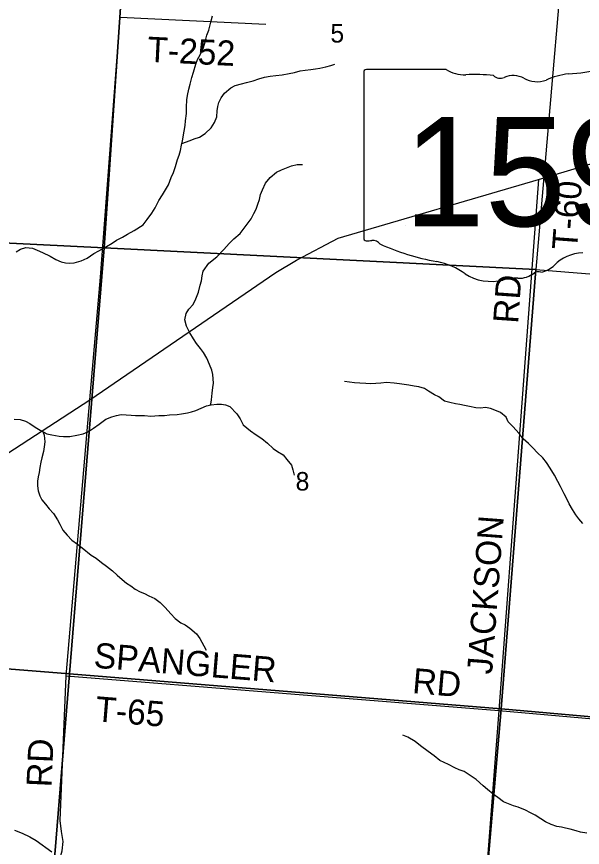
# Model space of a CAD drawing. Extents: x 0 to 42.5, y 0 to 22.
# Drawn here: x 5.809 to 6.449, y 17.595 to 18.534 of the extents above; entities that cross this region are included whole.
import ezdxf

# ---------------------------------------------------------------- set-up
doc = ezdxf.new("R2010")
doc.units = 0
for name, color, linetype in [('GM_X_Minor_River', 7, 'Continuous'), ('GM_X_Section', 7, 'Continuous'), ('GM_X_Section_Text', 7, 'Continuous'), ('GM_X_State_Location', 7, 'Continuous'), ('GM_X_State_Route', 7, 'Continuous'), ('GM_X_State_Shield', 7, 'Continuous'), ('GM_X_Township_Road', 7, 'Continuous'), ('GM_X_Township_Road_Text', 7, 'Continuous')]:
    doc.layers.add(name, color=color, linetype=linetype)

msp = doc.modelspace()

# ---------------------------------------------------------------- linework, layer by layer
at = {"layer": 'GM_X_Minor_River'}
for points in [[(5.80862, 18.268), (5.8136, 18.271), (5.81992, 18.27286), (5.82738, 18.27223), (5.83273, 18.2701), (5.83865, 18.26721), (5.84725, 18.26335), (5.85355, 18.25951), (5.85986, 18.25699), (5.86464, 18.25563), (5.86942, 18.25521), (5.87458, 18.25556), (5.88224, 18.25778), (5.88913, 18.26096), (5.89679, 18.26622), (5.90215, 18.26922), (5.91096, 18.27429), (5.91748, 18.27804), (5.92226, 18.28123), (5.92916, 18.28479), (5.9349, 18.28798), (5.94237, 18.2923), (5.95233, 18.29868), (5.95713, 18.30473), (5.96231, 18.31191), (5.96595, 18.31796), (5.97018, 18.3261), (5.97421, 18.33271), (5.98112, 18.34368), (5.9842, 18.35221), (5.9867, 18.35789), (5.98901, 18.36452), (5.99151, 18.37248), (5.99324, 18.37741), (5.99459, 18.38252), (5.99594, 18.38859), (5.99691, 18.39352), (5.99885, 18.40453), (6.00001, 18.41098), (6.0004, 18.41629), (6.00138, 18.42445), (6.00139, 18.43186), (6.00179, 18.43984), (6.00257, 18.44477), (6.0043, 18.45198), (6.00566, 18.45766), (6.00758, 18.46506), (6.00951, 18.47131), (6.01221, 18.48041), (6.01413, 18.48553), (6.01701, 18.49082), (6.02066, 18.49916), (6.02278, 18.5056), (6.02433, 18.513), (6.02683, 18.51887), (6.02953, 18.52929), (6.03088, 18.53479)], [(5.99631, 18.39046), (6.00552, 18.39384), (6.0103, 18.39571), (6.01605, 18.39775), (6.02256, 18.40189), (6.02946, 18.40829), (6.0333, 18.41416), (6.0358, 18.42079), (6.03639, 18.42762), (6.03697, 18.43236), (6.03813, 18.4371), (6.04062, 18.44241), (6.04465, 18.4475), (6.05155, 18.45353), (6.05672, 18.45616), (6.0638, 18.45819), (6.06954, 18.45948), (6.07682, 18.46133), (6.08332, 18.46356), (6.08983, 18.46541), (6.09615, 18.4667), (6.10265, 18.4676), (6.10992, 18.46831), (6.11757, 18.46958), (6.1237, 18.47106), (6.1302, 18.47272), (6.13575, 18.47363), (6.14226, 18.47434), (6.14742, 18.47506), (6.15221, 18.47579), (6.1591, 18.47726), (6.16465, 18.47893), (6.16943, 18.48041)], [(6.02825, 18.09502), (6.02897, 18.09602), (6.02994, 18.10095), (6.03053, 18.10817), (6.03131, 18.11462), (6.03189, 18.11974), (6.03171, 18.12468), (6.03115, 18.12944), (6.03021, 18.13438), (6.02754, 18.14086), (6.0245, 18.14772), (6.02088, 18.1542), (6.01744, 18.15898), (6.01267, 18.16452), (6.00924, 18.16967), (6.00524, 18.17635), (6.00143, 18.18398), (5.99973, 18.19121), (6.00108, 18.19823), (6.00396, 18.20314), (6.00913, 18.20842), (6.01221, 18.21505), (6.0149, 18.22263), (6.01683, 18.2304), (6.01837, 18.23533), (6.01915, 18.24083), (6.0205, 18.24614), (6.02683, 18.2554), (6.03565, 18.26256), (6.04389, 18.27086), (6.04964, 18.27746), (6.05501, 18.28274), (6.0621, 18.28896), (6.07476, 18.30558), (6.07783, 18.31145), (6.08033, 18.31637), (6.08225, 18.32206), (6.08418, 18.32717), (6.08515, 18.33305), (6.08764, 18.33816), (6.09091, 18.34574), (6.09609, 18.35216), (6.10318, 18.35818), (6.10892, 18.3608), (6.11467, 18.36304), (6.12022, 18.36528), (6.12653, 18.36675), (6.13285, 18.36671)], [(6.44987, 17.96077), (6.44548, 17.96612), (6.44204, 17.9709), (6.43823, 17.97681), (6.43461, 17.98311), (6.43233, 17.98825), (6.4289, 17.99436), (6.42471, 18.00275), (6.42166, 18.00846), (6.41766, 18.01552), (6.41289, 18.02353), (6.40889, 18.02983), (6.4045, 18.03537), (6.39839, 18.0413), (6.39362, 18.04628), (6.38847, 18.05125), (6.38255, 18.05661), (6.37778, 18.06254), (6.37072, 18.07057), (6.36557, 18.07573), (6.3631, 18.08126), (6.35679, 18.08643), (6.35049, 18.08914), (6.34552, 18.09107), (6.33978, 18.09206), (6.33424, 18.09153), (6.32869, 18.09157), (6.32181, 18.09333), (6.31607, 18.09451), (6.31091, 18.0955), (6.30594, 18.09611), (6.29925, 18.09787), (6.29351, 18.09943), (6.28683, 18.10403), (6.28205, 18.10654), (6.27537, 18.11076), (6.27059, 18.11365), (6.26428, 18.11559), (6.25893, 18.1162), (6.253, 18.11719), (6.24765, 18.11799), (6.24248, 18.11879), (6.23637, 18.11978), (6.22776, 18.12042), (6.22125, 18.11951), (6.21571, 18.11917), (6.21016, 18.11902), (6.20442, 18.11907), (6.19754, 18.1195), (6.19142, 18.11992), (6.18606, 18.12072), (6.18033, 18.12152)], [(5.80668, 18.07901), (5.81318, 18.0784), (5.8193, 18.07664), (5.82408, 18.07414), (5.83038, 18.06991), (5.83611, 18.06645), (5.84356, 18.06241), (5.8493, 18.06104), (5.85752, 18.05965), (5.8623, 18.05924), (5.86957, 18.05937), (5.8776, 18.06083), (5.88449, 18.0625), (5.89062, 18.06492), (5.89617, 18.06868), (5.90269, 18.07338), (5.91016, 18.07883), (5.91686, 18.08164), (5.92222, 18.08312), (5.92758, 18.08422), (5.93331, 18.08399), (5.93905, 18.08337), (5.94383, 18.08315), (5.9488, 18.08292), (5.95397, 18.08289), (5.96104, 18.08246), (5.97003, 18.08296), (5.97654, 18.0831), (5.98209, 18.08363), (5.99089, 18.08414), (5.99567, 18.08487), (6.00256, 18.08596), (6.00734, 18.08725), (6.01213, 18.08873), (6.01825, 18.09154), (6.02419, 18.09416), (6.02936, 18.09526), (6.03567, 18.09578), (6.04102, 18.09593), (6.0458, 18.09514), (6.05058, 18.0934), (6.05841, 18.08479), (6.06241, 18.07944), (6.06546, 18.07239), (6.07386, 18.06568), (6.08016, 18.06127), (6.08666, 18.05704), (6.09315, 18.05187), (6.09945, 18.04575), (6.10441, 18.04229), (6.11091, 18.03844)], [(5.83891, 18.06494), (5.8405, 18.06091), (5.84125, 18.05312), (5.84066, 18.04781), (5.83988, 18.0423), (5.83796, 18.03529), (5.8368, 18.03036), (5.83564, 18.02429), (5.83467, 18.0186), (5.83351, 18.01367), (5.83312, 18.00892), (5.83311, 18.0036), (5.83367, 17.9979), (5.83557, 17.99238), (5.83785, 17.98761), (5.84186, 17.98264), (5.84625, 17.97767), (5.85102, 17.97213), (5.8554, 17.96526), (5.85807, 17.96011), (5.86169, 17.95344), (5.86646, 17.9479), (5.8718, 17.94197), (5.8781, 17.93775), (5.88364, 17.93353), (5.89357, 17.9251), (5.8993, 17.92183), (5.90541, 17.91703), (5.91114, 17.91281), (5.91782, 17.90726), (5.92297, 17.90247), (5.92889, 17.89768), (5.93367, 17.89346), (5.93863, 17.89058), (5.94341, 17.88675), (5.94895, 17.88367), (5.95391, 17.88173), (5.95888, 17.87904), (5.96576, 17.87633), (5.97187, 17.87153), (5.97741, 17.86599), (5.9837, 17.85872), (5.98886, 17.85356), (5.99516, 17.84876), (6.00013, 17.84645), (6.00509, 17.8428), (6.01273, 17.83629), (6.01654, 17.83094), (6.0213, 17.82255), (6.02359, 17.8176)], [(6.11091, 18.03844), (6.1151, 18.03328), (6.12044, 18.02679), (6.12177, 18.02165), (6.12348, 18.01575)], [(6.45447, 17.61067), (6.44739, 17.61205), (6.44242, 17.61342), (6.43573, 17.61518), (6.43038, 17.61654), (6.4256, 17.61753), (6.42063, 17.61851), (6.41413, 17.62046), (6.40782, 17.62373), (6.40228, 17.627), (6.39598, 17.63123), (6.39082, 17.63392), (6.3849, 17.63682), (6.37687, 17.6401), (6.37133, 17.64185), (6.36598, 17.64417), (6.36024, 17.6463), (6.35375, 17.6511), (6.3484, 17.65475), (6.34191, 17.66011), (6.33714, 17.66451), (6.32931, 17.67141), (6.32225, 17.67621), (6.31556, 17.68044), (6.31002, 17.68257), (6.30505, 17.68488), (6.29798, 17.68835), (6.29301, 17.69067), (6.28823, 17.69317), (6.28174, 17.69815), (6.27487, 17.70333), (6.26608, 17.70966), (6.26036, 17.71446), (6.25195, 17.71926), (6.24641, 17.72158)]]:
    msp.add_lwpolyline(points, dxfattribs=at)
at = {"layer": 'GM_X_Section'}
for points in [[(5.87382, 18.8051), (5.94404, 18.79959), (5.90839, 18.27246), (5.40504, 18.29767), (5.40881, 18.34747), (5.44269, 18.83716)], [(6.3846, 18.76355), (6.44097, 18.75889), (6.3966, 18.24824), (5.90839, 18.27246), (5.94404, 18.79959)], [(5.90839, 18.27246), (5.86904, 17.79112), (5.36991, 17.83091), (5.37033, 17.84454), (5.40504, 18.29767)], [(6.3966, 18.24824), (6.35739, 17.75137), (5.86904, 17.79112), (5.90839, 18.27246)], [(6.8982, 18.20769), (6.86541, 17.70644), (6.35739, 17.75137), (6.3966, 18.24824)], [(5.36991, 17.83091), (5.86904, 17.79112), (5.82691, 17.27078), (5.32925, 17.29977), (5.33145, 17.33215)], [(5.86904, 17.79112), (6.35739, 17.75137), (6.31416, 17.24467), (5.82691, 17.27078)], [(6.35739, 17.75137), (6.86541, 17.70644), (6.82143, 17.20258), (6.31416, 17.24467)]]:
    msp.add_lwpolyline(points, close=True, dxfattribs=at)
at = {"layer": 'GM_X_State_Route'}
for points in [[(5.36316, 17.75308), (5.49056, 17.83998), (5.89196, 18.10067), (6.10243, 18.24475), (6.12608, 18.25885), (6.17328, 18.28372), (6.39962, 18.34993), (6.70955, 18.44268), (6.75629, 18.44764), (6.83846, 18.45633), (6.85666, 18.45975), (6.8701, 18.46641), (6.90871, 18.49397), (6.91343, 18.49734)], [(5.80677, 17.6142), (5.81569, 17.61093), (5.82412, 17.60687), (5.83126, 17.6025), (5.84906, 17.58984)]]:
    msp.add_lwpolyline(points, dxfattribs=at)
at = {"layer": 'GM_X_State_Shield'}
for p, q in [((6.20202, 18.47105), (6.20202, 18.28389)), ((6.29532, 18.47427), (6.20505, 18.47427))]:
    msp.add_line(p, q, dxfattribs=at)
for centre, major_axis, start_param, end_param in [((6.40045, 18.72943), (0.32688, 0), 4.814394, 5.042369), ((6.20555, 18.47145), (0.00357, 0), 1.712693, 3.28349), ((6.31682, 18.496), (0.03464, 0), 4.042523, 4.731795), ((6.3283, 18.3692), (0.12434, 0), 1.404758, 1.657858), ((6.35653, 18.47242), (0.00999, 0), 3.836095, 5.185415), ((6.3712, 18.45079), (0.02077, 0), 0.950623, 2.079405), ((6.44215, 18.4171), (0.06576, 0), 1.699011, 2.107814), ((6.39801, 18.48046), (0.02499, 0), 4.081561, 5.145723), ((6.20558, 18.28348), (0.0036, 0), 3.00124, 4.508301), ((6.20613, 18.30263), (0.02749, 0), 4.665946, 4.897461), ((6.21175, 18.27309), (0.00991, 0), 0.519207, 1.627899), ((6.33691, 18.44125), (0.23605, 0), 4.195997, 4.488961), ((6.45324, 18.23135), (0.04478, 0), 1.647645, 2.488434), ((6.26653, 18.19981), (0.07386, 0), 0.823519, 1.323587), ((6.39651, 18.26575), (0.02641, 0), 4.937069, 5.64225), ((6.34641, 18.27216), (0.04687, 0), 4.026481, 4.996735), ((6.37692, 18.25815), (0.02497, 0), 4.691044, 5.507374), ((6.3995, 18.24002), (0.00703, 0), 1.147584, 2.315152), ((6.37349, 18.20746), (0.03851, 0), 1.495662, 1.94098)]:
    msp.add_ellipse(centre, major_axis=major_axis, ratio=0.8, start_param=start_param, end_param=end_param, dxfattribs=at)
at = {"layer": 'GM_X_Township_Road'}
for p, q in [((5.92637, 18.53333), (6.09129, 18.52546)), ((6.35504, 17.74968), (6.31564, 17.24323))]:
    msp.add_line(p, q, dxfattribs=at)
for points in [[(5.89196, 18.10067), (5.90408, 18.2393), (5.92637, 18.53333), (5.94459, 18.80049)], [(6.39962, 18.34993), (6.37788, 18.05724), (6.35504, 17.74968)], [(5.8584, 17.58286), (5.86102, 17.59099), (5.86189, 17.60147), (5.8599, 17.61256), (5.8584, 17.62516), (5.86549, 17.78868), (5.89196, 18.10067)], [(5.86549, 17.78868), (6.35504, 17.74968), (6.86298, 17.70481), (7.3592, 17.66367)]]:
    msp.add_lwpolyline(points, dxfattribs=at)

# ---------------------------------------------------------------- texts
at = {"layer": 'GM_X_Section_Text'}
for s, p in [('5', (6.16432, 18.50471)), ('8', (6.12495, 17.9982))]:
    msp.add_text(s, height=0.02093, rotation=0.00001, dxfattribs=at).set_placement(p)
at = {"layer": 'GM_X_State_Location'}
for s in ['s', 'r']:
    msp.add_text(s, height=0.0000947, dxfattribs=at).set_placement((6.28254, 18.30436))
msp.add_text('159', height=0.0000947, rotation=0.00001, dxfattribs=at).set_placement((6.24911, 18.29747))
at = {"layer": 'GM_X_State_Shield'}
msp.add_text('159', height=0.123297, dxfattribs=at).set_placement((6.24735, 18.29709))
at = {"layer": 'GM_X_Township_Road_Text'}
for s, rotation, p in [('T-252', 357.19408, (5.9567, 18.48308)), ('T-60', 85.7632, (6.44329, 18.2695)), ('RD', 86.02095, (6.37672, 18.18644)), ('JACKSON', 85.71846, (6.34713, 17.78983)), ('SPANGLER', 355.34667, (5.89585, 17.79806)), ('RD', 355.07376, (6.25632, 17.76929)), ('T-65', 355.38346, (5.89764, 17.73735)), ('RD', 87.53133, (5.84879, 17.6624))]:
    msp.add_text(s, height=0.028409, rotation=rotation, dxfattribs=at).set_placement(p)

doc.saveas('drawing.dxf')
